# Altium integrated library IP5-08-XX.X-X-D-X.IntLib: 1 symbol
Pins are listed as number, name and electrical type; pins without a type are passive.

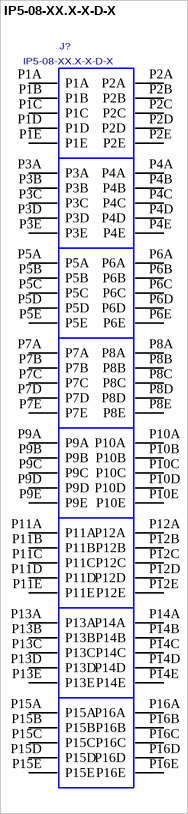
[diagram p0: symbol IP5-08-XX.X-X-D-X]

## IP5-08-XX.X-X-D-X
designator J?
TERMINAL ARRAY ASSEMBLY, IP5 CONNECTOR.; MANUFACTURER: SAMTEC
footprint IP5-08-XX.X-X-D-X
pins: P1A, P1B, P1C, P1D, P1E, P2A, P2B, P2C, P2D, P2E, P3A, P3B, P3C, P3D, P3E, P4A, P4B, P4C, P4D, P4E, P5A, P5B, P5C, P5D, P5E, P6A, P6B, P6C, P6D, P6E, P7A, P7B, P7C, P7D, P7E, P8A, P8B, P8C, P8D, P8E, P9A, P9B, P9C, P9D, P9E, P10A, P10B, P10C, P10D, P10E, P11A, P11B, P11C, P11D, P11E, P12A, P12B, P12C, P12D, P12E, P13A, P13B, P13C, P13D, P13E, P14A, P14B, P14C, P14D, P14E, P15A, P15B, P15C, P15D, P15E, P16A, P16B, P16C, P16D, P16E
